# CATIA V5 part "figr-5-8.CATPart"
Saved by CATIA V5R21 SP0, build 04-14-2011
Part number: Part1
Bounding box of the stored display mesh (mm): x 0 to 150, y -70 to 70, z -150 to 69.804
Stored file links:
  D:\CATIA V5R21 E-RESOURCES\CATIA-V5R21\catia-v5r21-prt\c05-catia-v5r20-prt\catia-v5r21-figr-5-8.CATPart
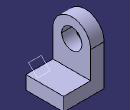
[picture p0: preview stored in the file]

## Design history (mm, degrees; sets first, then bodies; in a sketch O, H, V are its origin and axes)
Set1
  Plane1: type Angle, RefPlane face of Pad2, Direction edge of Pad2, Angle -45
Body1 (main body)
  Sketch1 on yz-plane, origin (0, 0, 0), H (0, 1, 0), V (0, 0, 1)
    arc A1 centre (0, 0) radius 70 from (70, 0) to (-70, 0) ccw
    point P1 (70, 0)
    point P2 (-70, 0)
    line L1 (-70, 0) -> (-70, -150)
    line L2 (-70, -150) -> (70, -150)
    line L3 (70, -150) -> (70, 0)
    circle A2 centre (0, 0) radius 37.5
    radius A1 = 70
    radius A2 = 37.5
    distance O L2 = 150
    coincidence: P1 H, P2 H
    tangency: L1 A1, L3 A1
    horizontal: L2 H
  Pad1: profile Sketch1, direction (1, 0, 0), length 50
  Sketch2 on face of Pad1, origin (50, 0, 0), H (0, 1, 0), V (0, 0, 1)
    line L1 (-70, -150) -> (70, -150)
    line L2 (70, -150) -> (70, -100)
    line L3 (70, -100) -> (-70, -100)
    line L4 (-70, -100) -> (-70, -150)
    reference projected line E1 (-70, -150) -> (70, -150) from edge [face of Pad1 | face of Pad1]
    reference projected line E2 (-70, 0) -> (-70, -150) from edge [face of Pad1 | face of Pad1]
    reference projected line E3 (70, -150) -> (70, 0) from edge [face of Pad1 | face of Pad1]
    length L2 = 50
    horizontal: L1 H, L3 H
    vertical: L2 V, L4 V
    coincidence: L1 E1, E2 L4, L2 E3
  Pad2: profile Sketch2, direction (1, 0, 0), length 100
